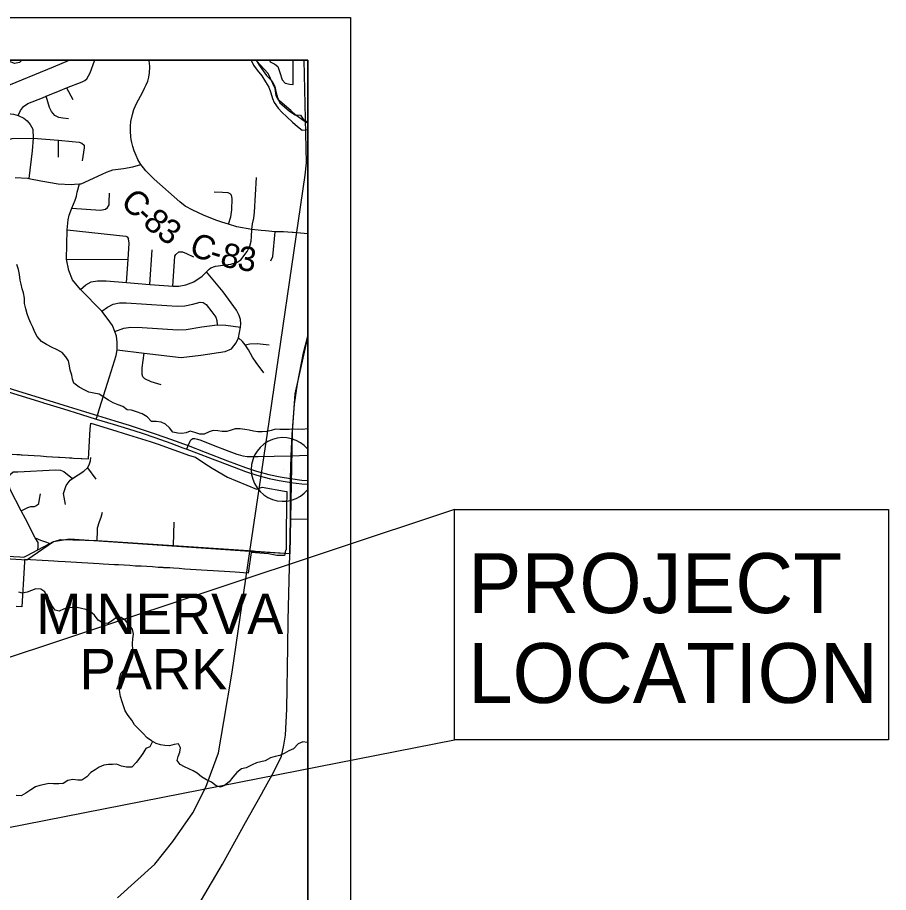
# Model space of a CAD drawing. Extents: x 0 to 34, y 0 to 22.
# Drawn here: x 18.887 to 20.921, y 18.152 to 20.196 of the extents above; entities that cross this region are included whole.
import ezdxf

# ---------------------------------------------------------------- set-up
doc = ezdxf.new("R2010")
doc.units = 0
for name, color, linetype in [('GM_X_City_Street', 7, 'Continuous'), ('GM_X_Corporation', 7, 'Continuous'), ('GM_X_Corporation_Text', 7, 'Continuous'), ('GM_X_County_Road', 7, 'Continuous'), ('GM_X_County_Road_Text', 7, 'Continuous'), ('GM_X_Major_River', 7, 'Continuous'), ('GM_X_Minor_Lake', 7, 'Continuous'), ('GM_X_Minor_River', 7, 'Continuous'), ('GM_X_Rail_Line', 7, 'Continuous'), ('GM_X_State_Route', 7, 'Continuous'), ('GM_X_Unincorporated_Location', 7, 'Continuous'), ('GM_X_US_Shield', 7, 'Continuous'), ('SH_Data', 7, 'Continuous'), ('SH_Text', 7, 'Continuous')]:
    doc.layers.add(name, color=color, linetype=linetype)

msp = doc.modelspace()

# ---------------------------------------------------------------- linework, layer by layer
at = {"layer": 'GM_X_City_Street'}
for p, q in [((19.0016, 20.0321), (19.0159, 20.0046)), ((18.9827, 19.8704), (18.9827, 19.9098)), ((19.1957, 19.5728), (19.2013, 19.6537)), ((19.0016, 19.6315), (19.1453, 19.6307)), ((19.0501, 19.1445), (19.0701, 19.1178)), ((19.2514, 18.9628), (19.2529, 19.0173)), ((19.4428, 18.9499), (19.5229, 18.9439))]:
    msp.add_line(p, q, dxfattribs=at)
for points in [[(18.8306, 19.9754), (18.8353, 20.0018), (18.8383, 20.0193), (18.843, 20.0256), (18.8537, 20.033), (18.9709, 20.0814), (19.0061, 20.0956), (19.0094, 20.0965)], [(18.8888, 19.9674), (18.8942, 19.9791), (18.9008, 19.9885), (18.9112, 19.9959), (18.9449, 20.009), (18.9535, 20.0125), (18.9866, 20.0261), (19.0016, 20.0321), (19.0382, 20.046), (19.044, 20.0493), (19.0485, 20.0534), (19.0565, 20.0669), (19.0663, 20.0952), (19.0668, 20.0965)], [(18.5419, 20.0533), (18.5453, 20.0398), (18.5525, 20.0161), (18.5591, 20.0031), (18.5647, 19.9969), (18.5696, 19.9926), (18.5806, 19.9894), (18.6037, 19.9882), (18.6987, 19.9834), (18.7737, 19.979), (18.8306, 19.9754), (18.8493, 19.9742), (18.8637, 19.9725), (18.8777, 19.9703), (18.8888, 19.9674), (18.9019, 19.9615), (18.9097, 19.9549), (18.9168, 19.9468), (18.9225, 19.9355), (18.9238, 19.9147), (18.9214, 19.8852), (18.913, 19.8202)], [(19.0059, 19.96), (18.9927, 19.9614), (18.9832, 19.9627), (18.9738, 19.9674), (18.9663, 19.9767), (18.9616, 19.9859), (18.9535, 20.0125)], [(18.8564, 19.8814), (18.8594, 19.8992), (18.8621, 19.9064), (18.8664, 19.9116), (18.8748, 19.9134), (18.9238, 19.9147)], [(18.9238, 19.9147), (18.9827, 19.9098), (19.0149, 19.9071), (19.0312, 19.9049), (19.0372, 19.9028), (19.0425, 19.8978), (19.0424, 19.8917), (19.038, 19.8618)], [(18.8812, 19.8225), (18.91, 19.8208), (18.913, 19.8202), (18.9411, 19.8146), (18.9816, 19.8082), (19.012, 19.8065), (19.02, 19.8067), (19.0319, 19.8076), (19.0356, 19.8079), (19.0845, 19.8304), (19.0945, 19.8352), (19.103, 19.8385), (19.1095, 19.8406), (19.1346, 19.8439), (19.1565, 19.8473), (19.175, 19.8532)], [(19.4343, 19.7012), (19.4358, 19.714), (19.4388, 19.7278), (19.4407, 19.7413), (19.445, 19.823)], [(19.0708, 19.2583), (19.0735, 19.2667), (19.0785, 19.2827), (19.1014, 19.3568), (19.1169, 19.407), (19.1197, 19.4203), (19.1198, 19.4378), (19.118, 19.4516), (19.1143, 19.4631), (19.1085, 19.4765), (19.1026, 19.4857), (19.0939, 19.4969), (19.084, 19.51), (19.0337, 19.5613), (19.0152, 19.5837), (19.0068, 19.6053), (19.0016, 19.6315), (19.0027, 19.7004), (19.005, 19.7237), (19.0076, 19.7348), (19.0138, 19.7508), (19.0218, 19.7694), (19.0248, 19.7792), (19.0263, 19.7884), (19.0319, 19.8076)], [(19.0138, 19.7508), (19.0806, 19.7465), (19.0923, 19.7484), (19.0973, 19.7526), (19.1007, 19.7591), (19.101, 19.7648), (19.102, 19.7864)], [(19.3797, 19.7136), (19.385, 19.731), (19.3874, 19.747), (19.3885, 19.7732), (19.3866, 19.7816), (19.3834, 19.7843), (19.3788, 19.7865), (19.3655, 19.7879), (19.3458, 19.7884)], [(19.0027, 19.7004), (19.1402, 19.6856), (19.1433, 19.6838), (19.146, 19.6796)], [(19.0337, 19.5613), (19.0465, 19.5721), (19.059, 19.5786), (19.0735, 19.5809), (19.0936, 19.5814), (19.1416, 19.5774), (19.1957, 19.5728), (19.2394, 19.5692), (19.25, 19.5689), (19.2634, 19.5685), (19.2801, 19.5716), (19.2983, 19.5789), (19.318, 19.592), (19.3281, 19.6021), (19.3347, 19.6087), (19.3385, 19.6114), (19.3495, 19.6153), (19.3852, 19.6204), (19.4, 19.625), (19.4087, 19.6303), (19.423, 19.6496), (19.4293, 19.662), (19.4322, 19.6739), (19.4333, 19.6845), (19.4343, 19.7012)], [(19.4787, 19.6283), (19.4834, 19.6384), (19.4884, 19.6958)], [(19.1416, 19.5774), (19.1453, 19.6307), (19.1479, 19.669), (19.146, 19.6796)], [(19.25, 19.5689), (19.2542, 19.6391), (19.2569, 19.6429), (19.2633, 19.649), (19.2721, 19.6487), (19.2812, 19.6449), (19.298, 19.6374)], [(19.398, 19.5126), (19.3673, 19.5557), (19.3281, 19.6021)], [(19.084, 19.51), (19.0973, 19.52), (19.1099, 19.5264), (19.1247, 19.5296), (19.1407, 19.5296), (19.2355, 19.5232), (19.2601, 19.5217), (19.2779, 19.5231), (19.2967, 19.5267), (19.3133, 19.5316), (19.3207, 19.5302), (19.3273, 19.5256), (19.3406, 19.5089), (19.3502, 19.4966), (19.3527, 19.4886), (19.3531, 19.4784)], [(19.1197, 19.4203), (19.1823, 19.4123), (19.2692, 19.4019), (19.3152, 19.4078), (19.3722, 19.4161), (19.3863, 19.4222), (19.3976, 19.4362), (19.4026, 19.4483), (19.4076, 19.4729), (19.4084, 19.4809), (19.4075, 19.4911), (19.4045, 19.5001), (19.398, 19.5126)], [(19.1143, 19.4631), (19.1351, 19.4704), (19.1519, 19.4731), (19.1779, 19.4719), (19.2612, 19.4668), (19.2807, 19.4675), (19.3177, 19.4735), (19.3531, 19.4784), (19.3737, 19.4773), (19.4076, 19.4729)], [(19.4619, 19.366), (19.4439, 19.3902), (19.4355, 19.4031), (19.4262, 19.4201), (19.4189, 19.4315), (19.4121, 19.4398), (19.4026, 19.4483)], [(19.4189, 19.4315), (19.4296, 19.4342), (19.4467, 19.435), (19.4749, 19.4317)], [(19.2224, 19.3383), (19.1987, 19.3454), (19.1839, 19.3521), (19.1793, 19.3567), (19.1781, 19.3627), (19.178, 19.3776), (19.1823, 19.4123)], [(18.9989, 19.0589), (18.9944, 19.084), (19.0004, 19.1029), (19.0098, 19.1158), (19.0151, 19.1195), (19.042, 19.1368), (19.0501, 19.1445), (19.0542, 19.1513), (19.0573, 19.1604), (19.0581, 19.1687)], [(18.8707, 19.1294), (18.8768, 19.135), (18.8875, 19.1353), (18.9758, 19.1395), (18.9873, 19.1391), (18.995, 19.1357), (19.0151, 19.1195)], [(18.9343, 18.9526), (18.9352, 18.9597), (18.9349, 18.9696), (18.9281, 18.9806), (18.9052, 19.0251), (18.8958, 19.0442), (18.8697, 19.0938), (18.8653, 19.11), (18.8665, 19.1214), (18.8707, 19.1294)], [(18.8958, 19.0442), (18.911, 19.0515), (18.9182, 19.0541), (18.9262, 19.0541), (18.9316, 19.0563), (18.9366, 19.0608), (18.9385, 19.0707), (18.9409, 19.0836)], [(19.0733, 18.9743), (19.0738, 18.9973), (19.074, 19.0042), (19.0783, 19.0186), (19.0825, 19.0288), (19.0852, 19.0406)], [(18.7303, 18.945), (18.8923, 18.9362), (18.9014, 18.9359), (18.9095, 18.9392), (18.9343, 18.9526), (18.9625, 18.9678), (18.9693, 18.9715), (18.9792, 18.9748), (18.9883, 18.9767), (19.0733, 18.9743), (19.2514, 18.9628), (19.4378, 18.9503), (19.4428, 18.9499)], [(18.9281, 18.9806), (18.9402, 18.9755), (18.9543, 18.9705), (18.9625, 18.9678)]]:
    msp.add_lwpolyline(points, dxfattribs=at)
at = {"layer": 'GM_X_Corporation'}
for points in [[(19.5646, 13.6135), (19.5646, 19.9499), (19.5562, 19.9544), (19.5366, 19.968), (19.5248, 19.9795), (19.5102, 19.9918), (19.5044, 19.9968), (19.4954, 20.0044), (19.4913, 20.0146), (19.4883, 20.0303), (19.4719, 20.0658), (19.4447, 20.0952), (19.4432, 20.0965), (15.9043, 20.0965)], [(19.5646, 17.627), (19.5646, 20.0965), (18.3706, 20.0965)], [(18.8741, 19.1762), (18.8953, 19.1749), (18.8978, 19.1747), (18.9118, 19.1738), (18.926, 19.1729), (18.9404, 19.172), (18.9547, 19.1711), (18.9685, 19.1703), (18.9828, 19.1693), (18.9853, 19.1692), (18.9978, 19.1684), (19.0081, 19.1678), (19.0138, 19.1674), (19.0176, 19.1672), (19.0527, 19.165), (19.0567, 19.2343), (19.0578, 19.2486), (19.1066, 19.2335), (19.1458, 19.2214), (19.1967, 19.2056), (19.2154, 19.1998), (19.2883, 19.1731), (19.3022, 19.1695), (19.3245, 19.1541), (19.3418, 19.1438), (19.3775, 19.1227), (19.4449, 19.0941), (19.458, 19.0991), (19.5102, 19.0897), (19.5159, 19.0886), (19.5151, 19.0498), (19.5141, 18.9991), (19.5143, 18.9741), (19.5144, 18.9525), (19.5128, 18.9509), (19.5102, 18.9391), (19.4924, 18.9398), (19.473, 18.9437), (19.4329, 18.9462), (19.4258, 18.898), (19.4149, 18.899), (19.405, 18.8996), (19.3948, 18.9003), (19.3824, 18.9011), (19.3699, 18.9019), (19.3565, 18.9028), (19.3436, 18.9036), (19.3301, 18.9045), (19.3169, 18.9053), (19.3038, 18.9062), (19.2906, 18.907), (19.2775, 18.9078), (19.2641, 18.9087), (19.2509, 18.9095), (19.2423, 18.9103), (19.2288, 18.911), (19.2267, 18.9112), (19.2156, 18.9118), (19.2023, 18.9126), (19.189, 18.9134), (19.1758, 18.9142), (19.1625, 18.9149), (19.1494, 18.9157), (19.1362, 18.9165), (19.1225, 18.9173), (19.1132, 18.9177), (19.0869, 18.9192), (19.0777, 18.9198), (19.0644, 18.9206), (19.0512, 18.9214), (19.0373, 18.9222), (19.0243, 18.9229), (19.0115, 18.9237), (18.9984, 18.9245), (18.9822, 18.9254), (18.9718, 18.926), (18.9585, 18.9268), (18.9036, 18.9301), (18.9033, 18.9248), (18.9024, 18.9112), (18.8967, 18.8192), (18.8838, 18.82)], [(18.8741, 19.1762), (18.892, 19.1751), (18.8978, 19.1747), (18.9118, 19.1738), (18.926, 19.1729), (18.9404, 19.172), (18.9547, 19.1711), (18.9685, 19.1703), (18.9828, 19.1693), (18.9853, 19.1692), (18.9978, 19.1684), (19.0081, 19.1678), (19.0138, 19.1674), (19.0176, 19.1672), (19.0368, 19.1659), (19.0527, 19.165), (19.0567, 19.2343), (19.0578, 19.2486), (19.1066, 19.2335), (19.1458, 19.2214), (19.1967, 19.2056), (19.2154, 19.1998), (19.2883, 19.1731), (19.3022, 19.1695), (19.3245, 19.1541), (19.3418, 19.1438), (19.3775, 19.1227), (19.4449, 19.0941), (19.458, 19.0991), (19.5102, 19.0897), (19.5159, 19.0886), (19.5151, 19.0498), (19.5141, 18.9991), (19.5143, 18.9741), (19.5144, 18.9525), (19.5128, 18.9509), (19.5102, 18.9391), (19.4924, 18.9398), (19.473, 18.9437), (19.4329, 18.9462), (19.4258, 18.898), (19.4149, 18.899), (19.405, 18.8996), (19.3948, 18.9003), (19.3824, 18.9011), (19.3699, 18.9019), (19.3565, 18.9028), (19.3436, 18.9036), (19.3301, 18.9045), (19.3169, 18.9053), (19.3038, 18.9062), (19.2906, 18.907), (19.2775, 18.9078), (19.2641, 18.9087), (19.2509, 18.9095), (19.2423, 18.9103), (19.2288, 18.911), (19.2267, 18.9112), (19.2156, 18.9118), (19.2023, 18.9126), (19.189, 18.9134), (19.1758, 18.9142), (19.1625, 18.9149), (19.1494, 18.9157), (19.1362, 18.9165), (19.1225, 18.9173), (19.1132, 18.9177), (19.0869, 18.9192), (19.0777, 18.9198), (19.0644, 18.9206), (19.0512, 18.9214), (19.0373, 18.9222), (19.0243, 18.9229), (19.0115, 18.9237), (18.9984, 18.9245), (18.9822, 18.9254), (18.9718, 18.926), (18.9585, 18.9268), (18.9036, 18.9301), (18.9033, 18.9248), (18.9024, 18.9112), (18.8967, 18.8192), (18.8838, 18.82)]]:
    msp.add_lwpolyline(points, dxfattribs=at)
at = {"layer": 'GM_X_County_Road'}
for p, q in [((19.5646, 19.6911), (19.5478, 19.6925)), ((19.5242, 19.0254), (19.5646, 19.0247))]:
    msp.add_line(p, q, dxfattribs=at)
for points in [[(19.1811, 19.8453), (19.175, 19.8532), (19.1682, 19.8649), (19.164, 19.8742), (19.1617, 19.8795), (19.1595, 19.885), (19.1563, 19.895), (19.154, 19.9043), (19.1523, 19.9114), (19.1516, 19.9173), (19.1507, 19.931), (19.1506, 19.9426), (19.1514, 19.9533), (19.1551, 19.9702), (19.1586, 19.9813), (19.1646, 19.9956), (19.1739, 20.013), (19.1793, 20.0226), (19.1838, 20.0313), (19.1877, 20.0394), (19.1911, 20.048), (19.1934, 20.0572), (19.1952, 20.0671), (19.1956, 20.0814), (19.195, 20.0902), (19.1938, 20.0965)], [(19.4562, 19.699), (19.4343, 19.7012), (19.3988, 19.7077), (19.3797, 19.7136), (19.3644, 19.718), (19.3504, 19.723), (19.3215, 19.7346), (19.2963, 19.7465), (19.2782, 19.7555), (19.2656, 19.7655), (19.2059, 19.819), (19.1866, 19.8381), (19.1811, 19.8453)], [(19.5281, 19.6941), (19.5077, 19.6955), (19.4884, 19.6958), (19.4661, 19.698), (19.4562, 19.699)], [(19.5478, 19.6925), (19.531, 19.6939), (19.5281, 19.6941)], [(19.2821, 19.1878), (19.2856, 19.1963), (19.2898, 19.2065), (19.292, 19.21), (19.2962, 19.2125), (19.3007, 19.213), (19.3074, 19.2113), (19.315, 19.2086), (19.3441, 19.1974), (19.38, 19.1834), (19.399, 19.1765)], [(19.399, 19.1765), (19.402, 19.1755), (19.4132, 19.1724), (19.4231, 19.171), (19.449, 19.171), (19.4866, 19.1716), (19.526, 19.1722), (19.5646, 19.1737)]]:
    msp.add_lwpolyline(points, dxfattribs=at)
at = {"layer": 'GM_X_Major_River'}
for points in [[(19.4327, 20.0965), (19.4376, 20.0854), (19.4467, 20.0732), (19.4572, 20.0599), (19.4663, 20.0462), (19.4738, 20.0336), (19.4783, 20.0203), (19.482, 20.0074), (19.4861, 19.9979), (19.4959, 19.9849), (19.5039, 19.9754), (19.5156, 19.964), (19.5292, 19.9517), (19.5405, 19.9414), (19.5518, 19.9334), (19.5646, 19.9344)], [(19.4446, 20.0965), (19.4513, 20.085), (19.4607, 20.0717), (19.4686, 20.0606), (19.4818, 20.048), (19.4875, 20.0355), (19.4901, 20.0237), (19.4942, 20.0092)], [(19.4942, 20.0092), (19.4994, 19.9974), (19.51, 19.9879), (19.5221, 19.9776), (19.5353, 19.9688), (19.5474, 19.9684), (19.5557, 19.9562), (19.5646, 19.9525)]]:
    msp.add_lwpolyline(points, dxfattribs=at)
at = {"layer": 'GM_X_Minor_Lake'}
msp.add_line((19.5306, 20.0398), (19.5305, 20.0965), dxfattribs=at)
msp.add_lwpolyline([(19.4752, 20.0965), (19.4769, 20.0927), (19.4878, 20.0877), (19.4946, 20.0823), (19.4998, 20.0682), (19.5046, 20.0507), (19.5121, 20.0427), (19.5227, 20.041), (19.5306, 20.0398)], dxfattribs=at)
at = {"layer": 'GM_X_Minor_River'}
for points in [[(18.8969, 20.0965), (18.8912, 20.0915), (18.8802, 20.0886), (18.8703, 20.0925), (18.8548, 20.09), (18.8445, 20.0817), (18.8349, 20.075), (18.8235, 20.0667), (18.8105, 20.0608), (18.8007, 20.0574), (18.79, 20.0522), (18.7782, 20.0482), (18.768, 20.0471), (18.757, 20.0446), (18.7456, 20.0405), (18.7357, 20.0357), (18.7254, 20.0377), (18.7152, 20.0355), (18.7057, 20.0341), (18.6955, 20.0395), (18.6918, 20.0414)], [(18.9331, 19.4512), (18.9275, 19.4615), (18.9223, 19.4726), (18.9182, 19.4821), (18.9134, 19.4928), (18.9093, 19.5043), (18.906, 19.5157), (18.9031, 19.5282), (18.9029, 19.5404), (18.9007, 19.5529), (18.8974, 19.5628), (18.8952, 19.5731), (18.893, 19.583), (18.8912, 19.5959), (18.8894, 19.6077), (18.885, 19.6196)], [(19.5646, 19.2355), (19.5519, 19.2342), (19.5421, 19.2347), (19.5216, 19.2341), (19.5106, 19.2338), (19.4996, 19.2339), (19.489, 19.2344), (19.4795, 19.2315), (19.4689, 19.2293), (19.4583, 19.2283), (19.448, 19.2287), (19.4382, 19.23), (19.4276, 19.2323), (19.4174, 19.2336), (19.4072, 19.2352), (19.395, 19.2357), (19.3855, 19.2324), (19.3756, 19.229), (19.365, 19.2291), (19.3548, 19.2308), (19.3438, 19.2316), (19.3343, 19.2283), (19.3229, 19.2231), (19.3127, 19.2232), (19.3006, 19.2267), (19.29, 19.2299), (19.2805, 19.2261), (19.271, 19.2247), (19.2612, 19.2252), (19.2498, 19.2276), (19.2419, 19.2379), (19.2322, 19.246), (19.2224, 19.2506), (19.211, 19.2523), (19.2, 19.2527), (19.1899, 19.2631), (19.1782, 19.2704), (19.1646, 19.2751), (19.1533, 19.2794), (19.143, 19.2799), (19.1332, 19.2872), (19.1223, 19.2911), (19.1106, 19.2965), (19.0997, 19.3023), (19.0884, 19.3092), (19.0778, 19.3166), (19.0653, 19.319), (19.0536, 19.321), (19.0438, 19.326), (19.0306, 19.333), (19.0185, 19.3418), (19.0152, 19.3513), (19.0134, 19.3608), (19.0101, 19.3723), (19.0083, 19.3825), (19.0061, 19.394), (19.0001, 19.4035), (18.9911, 19.4135), (18.9783, 19.4204), (18.9678, 19.4258), (18.9549, 19.4328), (18.9429, 19.4398), (18.9331, 19.4512)], [(19.0361, 18.8157), (19.0259, 18.8177), (19.0142, 18.8181), (19.0039, 18.8171), (18.994, 18.8142), (18.9845, 18.8093), (18.9747, 18.8117), (18.9672, 18.8228), (18.962, 18.8327), (18.9553, 18.8438), (18.9508, 18.8544), (18.941, 18.8606), (18.9293, 18.8619), (18.9198, 18.8578), (18.9095, 18.8537), (18.8985, 18.8515), (18.8902, 18.8535)], [(19.5646, 18.5025), (19.5631, 18.5027), (19.5529, 18.5039), (19.5422, 18.4994), (19.5315, 18.4878), (19.5208, 18.4833), (19.5094, 18.477), (19.4995, 18.4725), (19.4889, 18.4699), (19.4775, 18.4666), (19.4649, 18.4595), (19.455, 18.457), (19.4448, 18.4548), (19.4349, 18.4507), (19.4208, 18.4432), (19.4098, 18.4414), (19.3987, 18.4324), (19.3899, 18.4215), (19.3811, 18.4109), (19.3704, 18.4023), (19.3609, 18.3982), (19.3507, 18.401), (19.3401, 18.4098), (19.3284, 18.4152), (19.3168, 18.4226), (19.3066, 18.4306), (19.2968, 18.4364), (19.2772, 18.4457), (19.2666, 18.4508), (19.2595, 18.4603), (19.2622, 18.4702), (19.2661, 18.48), (19.2677, 18.4899), (19.2625, 18.4998), (19.253, 18.498), (19.2416, 18.4951), (19.231, 18.4952), (19.2208, 18.4968), (19.211, 18.4999), (19.2, 18.5061), (19.1895, 18.5138), (19.1794, 18.5245), (19.1692, 18.5345), (19.1602, 18.5441), (19.1539, 18.5551), (19.1453, 18.5659), (19.1382, 18.5766), (19.1341, 18.5884), (19.1311, 18.5979), (19.1275, 18.6097), (19.1257, 18.6192), (19.1246, 18.6321), (19.1243, 18.6416), (19.1252, 18.6526), (19.1291, 18.6655), (19.1394, 18.6764), (19.1486, 18.6877), (19.1537, 18.6979), (19.1572, 18.7089), (19.1561, 18.7184), (19.1551, 18.7336), (19.156, 18.745), (19.1576, 18.7556), (19.1554, 18.7671), (19.1476, 18.7766), (19.1389, 18.7877), (19.1291, 18.7946), (19.1189, 18.7955), (19.109, 18.7876), (19.0976, 18.7805), (19.0866, 18.781), (19.0753, 18.7883), (19.0663, 18.7998), (19.0561, 18.8094), (19.0463, 18.8133), (19.0361, 18.8157)], [(19.202, 18.505), (19.1961, 18.4928), (19.1866, 18.4884), (19.1797, 18.477), (19.172, 18.4657), (19.164, 18.4559), (19.1536, 18.445), (19.1415, 18.4451), (19.1301, 18.4475), (19.1181, 18.4518), (19.1086, 18.4515), (19.0991, 18.4508), (19.0885, 18.4498), (19.0778, 18.445), (19.0679, 18.439), (19.0584, 18.4326), (19.0488, 18.4221), (19.037, 18.4146), (19.0275, 18.4147), (19.0158, 18.4159), (19.0044, 18.4134), (18.9937, 18.407), (18.9835, 18.4056), (18.9706, 18.4057), (18.9604, 18.407), (18.9501, 18.4044), (18.9391, 18.4018), (18.9288, 18.3989), (18.9178, 18.3918), (18.9067, 18.3839), (18.8957, 18.3783), (18.8839, 18.3788)]]:
    msp.add_lwpolyline(points, dxfattribs=at)
at = {"layer": 'GM_X_Rail_Line'}
for points in [[(19.1204, 18.1393), (19.2078, 18.218), (19.2497, 18.2713), (19.2966, 18.3385), (19.327, 18.3982), (19.3562, 18.4781), (19.3689, 18.5517), (19.3879, 18.6671), (19.4296, 18.9485), (19.4703, 19.2253), (19.559, 19.8279), (19.5616, 19.8571), (19.5564, 20.0965)], [(19.5646, 19.453), (19.5342, 19.3174), (19.5281, 19.2284), (19.5231, 18.9437), (19.4296, 18.9485)], [(19.4296, 18.9485), (19.0081, 18.9777), (18.9711, 18.971), (18.9084, 18.9284), (18.7304, 18.9398), (18.7017, 18.9189), (18.5698, 18.8911), (18.3471, 18.8115), (18.3021, 18.7598), (18.2868, 18.7506), (18.1787, 17.0582)]]:
    msp.add_lwpolyline(points, dxfattribs=at)
at = {"layer": 'GM_X_State_Route'}
msp.add_line((19.5229, 18.9439), (19.5242, 19.0254), dxfattribs=at)
for points in [[(18.4271, 19.4444), (18.4366, 19.4419), (18.4899, 19.4281), (18.5424, 19.4142), (18.6029, 19.3983), (18.6284, 19.3918), (18.6699, 19.3808), (18.7008, 19.3722), (18.7597, 19.3546), (18.8269, 19.3337), (18.8877, 19.315), (18.9458, 19.297), (18.9477, 19.2964), (18.994, 19.2822), (19.0066, 19.2783), (19.0362, 19.2692), (19.0708, 19.2583), (19.1106, 19.2461), (19.1459, 19.2353), (19.1778, 19.225), (19.2076, 19.2151), (19.2446, 19.202), (19.2727, 19.1913)], [(18.428, 19.4531), (18.4387, 19.4503), (18.4919, 19.4365), (18.5444, 19.4226), (18.605, 19.4067), (18.6304, 19.4002), (18.6725, 19.389), (18.703, 19.3805), (18.7594, 19.3637), (18.8295, 19.3421), (18.8868, 19.3243), (18.9503, 19.3048), (19.0054, 19.2876), (19.0355, 19.2784), (19.0735, 19.2667)], [(19.526, 19.1722), (19.5285, 19.2219), (19.5335, 19.293), (19.5408, 19.3409), (19.5545, 19.4127), (19.5646, 19.4519)], [(19.0735, 19.2667), (19.114, 19.2542), (19.1479, 19.2436), (19.178, 19.2341), (19.2108, 19.223), (19.2444, 19.2113), (19.2856, 19.1963)], [(19.2727, 19.1913), (19.2821, 19.1878), (19.3214, 19.1729)], [(19.2856, 19.1963), (19.3253, 19.1807), (19.3776, 19.1608), (19.4192, 19.1452), (19.4452, 19.1366), (19.4739, 19.1287), (19.5001, 19.1229), (19.5246, 19.119), (19.5507, 19.1154), (19.5646, 19.1146)], [(19.3214, 19.1729), (19.3253, 19.1715), (19.3767, 19.1519), (19.4194, 19.136), (19.4455, 19.1275), (19.4743, 19.1196), (19.4979, 19.1146), (19.5213, 19.1108)], [(19.5243, 19.1036), (19.5244, 19.1103), (19.5246, 19.119), (19.526, 19.1722)], [(19.5213, 19.1108), (19.5244, 19.1103), (19.5512, 19.1067), (19.5646, 19.106)], [(19.5242, 19.0254), (19.5241, 19.065), (19.5243, 19.1036)], [(19.5183, 18.7265), (19.5192, 18.7877), (19.5229, 18.9439)], [(19.4624, 18.3923), (19.4857, 18.4338), (19.5037, 18.4709), (19.5092, 18.4964), (19.513, 18.5195), (19.5161, 18.5806), (19.5183, 18.7265)], [(19.1244, 17.7964), (19.1354, 17.8159), (19.1813, 17.8975), (19.1908, 17.9127), (19.2221, 17.9688), (19.261, 18.0413), (19.3164, 18.1346), (19.3655, 18.2182), (19.4192, 18.3153), (19.4566, 18.3819), (19.4624, 18.3923)]]:
    msp.add_lwpolyline(points, dxfattribs=at)
at = {"layer": 'GM_X_Unincorporated_Location'}
msp.add_line((19.5071, 19.1406), (19.5071, 19.1406), dxfattribs=at)
at = {"layer": 'GM_X_US_Shield'}
msp.add_line((19.5646, 19.0934), (19.5646, 19.1877), dxfattribs=at)
msp.add_arc((19.5071, 19.1406), 0.0744, 39.3193, 320.6807, dxfattribs=at)
at = {"layer": 'SH_Data'}
for p, q in [((12.6646, 20.1965), (19.6646, 20.1965)), ((19.6646, 20.1965), (19.6646, 13.1965)), ((12.7646, 20.0965), (19.5646, 20.0965)), ((19.5646, 20.0965), (19.5646, 13.2965))]:
    msp.add_line(p, q, dxfattribs=at)
at = {"layer": 'SH_Text'}
for points in [[(19.9075, 19.0471), (15.947, 17.7301), (19.9075, 18.5087)], [(19.9075, 19.0471), (20.9208, 19.0471), (20.9208, 18.5087), (19.9075, 18.5087)]]:
    msp.add_lwpolyline(points, close=True, dxfattribs=at)

# ---------------------------------------------------------------- texts
at = {"layer": 'GM_X_Corporation_Text'}
for s, p in [('MINERVA', (18.9307, 18.7558)), ('PARK', (19.032, 18.6266))]:
    msp.add_text(s, height=0.0947, rotation=0, dxfattribs=at).set_placement(p)
at = {"layer": 'GM_X_County_Road_Text'}
for s, rotation, p in [('C', 317.0734, (19.1246, 19.7613)), ('-', 318.0911, (19.1593, 19.729)), ('8', 318.6527, (19.177, 19.7132)), ('3', 325.913, (19.2092, 19.6854)), ('C', 338.9661, (19.2848, 19.6435)), ('8', 345.681, (19.3575, 19.6173)), ('-', 341.9582, (19.3314, 19.6257)), ('3', 352.6608, (19.3988, 19.6072))]:
    msp.add_text(s, height=0.0568, rotation=rotation, dxfattribs=at).set_placement(p)
at = {"layer": 'SH_Text'}
for s, p in [('PROJECT ', (19.9388, 18.8049)), ('LOCATION', (19.9388, 18.5949))]:
    msp.add_text(s, height=0.14, dxfattribs=at).set_placement(p)

doc.saveas('drawing.dxf')
